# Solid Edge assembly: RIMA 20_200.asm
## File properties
Title: Zylinder
Author: ahadarics
Template: iso metric assembly.asm
Last saved by: ahadarics
Revision: 15
Application: Solid Edge
Username: ahadarics
Dokumentum tartalom típus: 1
Document Number: RIMA 20/200
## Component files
Profilrohr.par
Kolbenstange.par
Kit_1.par
Kit_2.par
Mutter_1.par
Mutter_2.par
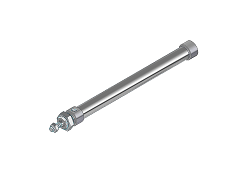
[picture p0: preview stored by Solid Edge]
